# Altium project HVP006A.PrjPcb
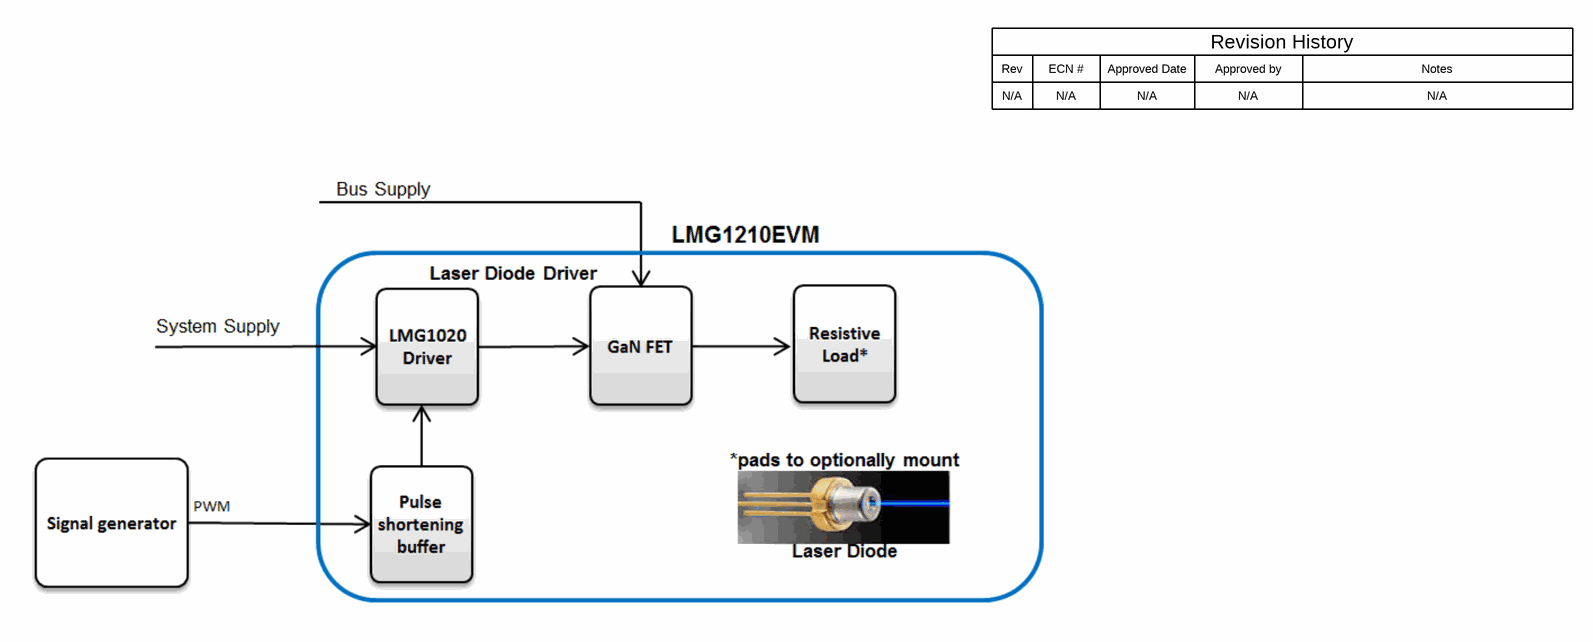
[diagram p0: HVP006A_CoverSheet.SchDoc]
CopyrightYear: 2017; EVM_orderable_num: LMG1020EVM-006; PCB_Layout: Alberto Doronzo; PCB_Rev: A; PRJ_Customer: Public Release; PRJ_Engineer: Alberto Doronzo; PRJ_Number: HPV006; PRJ_Title: LMG1020EVM; SCH_Rev: A; TechSupport: http://www.ti.com/support; TID: N/A
3 sheets, 56 parts. Net scope: global (net labels, ports and power ports of the same name join across sheets).
Board file: HVP006A.PcbDoc
Sheets:
  HVP006A_CoverSheet.SchDoc
  HVP006A.SchDoc
  HVP006A_EVM_Hardware.SchDoc

## Sheet HVP006A_CoverSheet.SchDoc
size 431 x 279 mm; Date: Not shown in title block; ApprovedBy: Not shown in title block; CheckedBy: Not shown in title block; Author: Not shown in title block; CompanyName: Not shown in title block; Engineer: Not shown in title block; Organization: Not shown in title block; Address1: Not shown in title block; Address2: Not shown in title block; Address3: Not shown in title block; Address4: Not shown in title block; DocumentNumber: 1; Revision: Use project parameter SCH_Rev; SheetNumber: 1; SheetTotal: 3; PageSetup: Record=PageOptions¦CenterHorizontal=True¦CenterVertical=True¦PrintScale=1.00¦XCorrection=1.00¦YCorrection=1.00¦PrintKind=0¦BorderSize=5000000¦LeftOffset=0¦BottomOffset=0¦Orientation=2¦PaperLength=1000¦PaperWidth=1000¦Scale=100¦PaperSource=15¦PrintQuality=600¦MediaType=1¦DitherType=10¦PaperKind=Letter¦PrintScaleMode=1

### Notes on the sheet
- Rev
- N/A
- ECN #
- Approved Date
- Approved by
- Revision History
- Notes

## Sheet HVP006A.SchDoc
size 431 x 279 mm; Date: Not shown in title block; ApprovedBy: Not shown in title block; CheckedBy: Not shown in title block; Author: Not shown in title block; CompanyName: Not shown in title block; Engineer: Not shown in title block; Organization: Not shown in title block; Address1: Not shown in title block; Address2: Not shown in title block; Address3: Not shown in title block; Address4: Not shown in title block; DocumentNumber: 1; Revision: Use project parameter SCH_Rev; SheetNumber: 2; SheetTotal: 3; PageSetup: Record=PageOptions¦CenterHorizontal=True¦CenterVertical=True¦PrintScale=0.64¦XCorrection=1.00¦YCorrection=1.00¦PrintKind=0¦BorderSize=5000000¦LeftOffset=0¦BottomOffset=0¦Orientation=2¦PaperLength=1000¦PaperWidth=1000¦Scale=100¦PaperSource=15¦PrintQuality=600¦MediaType=1¦DitherType=10¦PrintScaleMode=1¦PaperKind=Letter
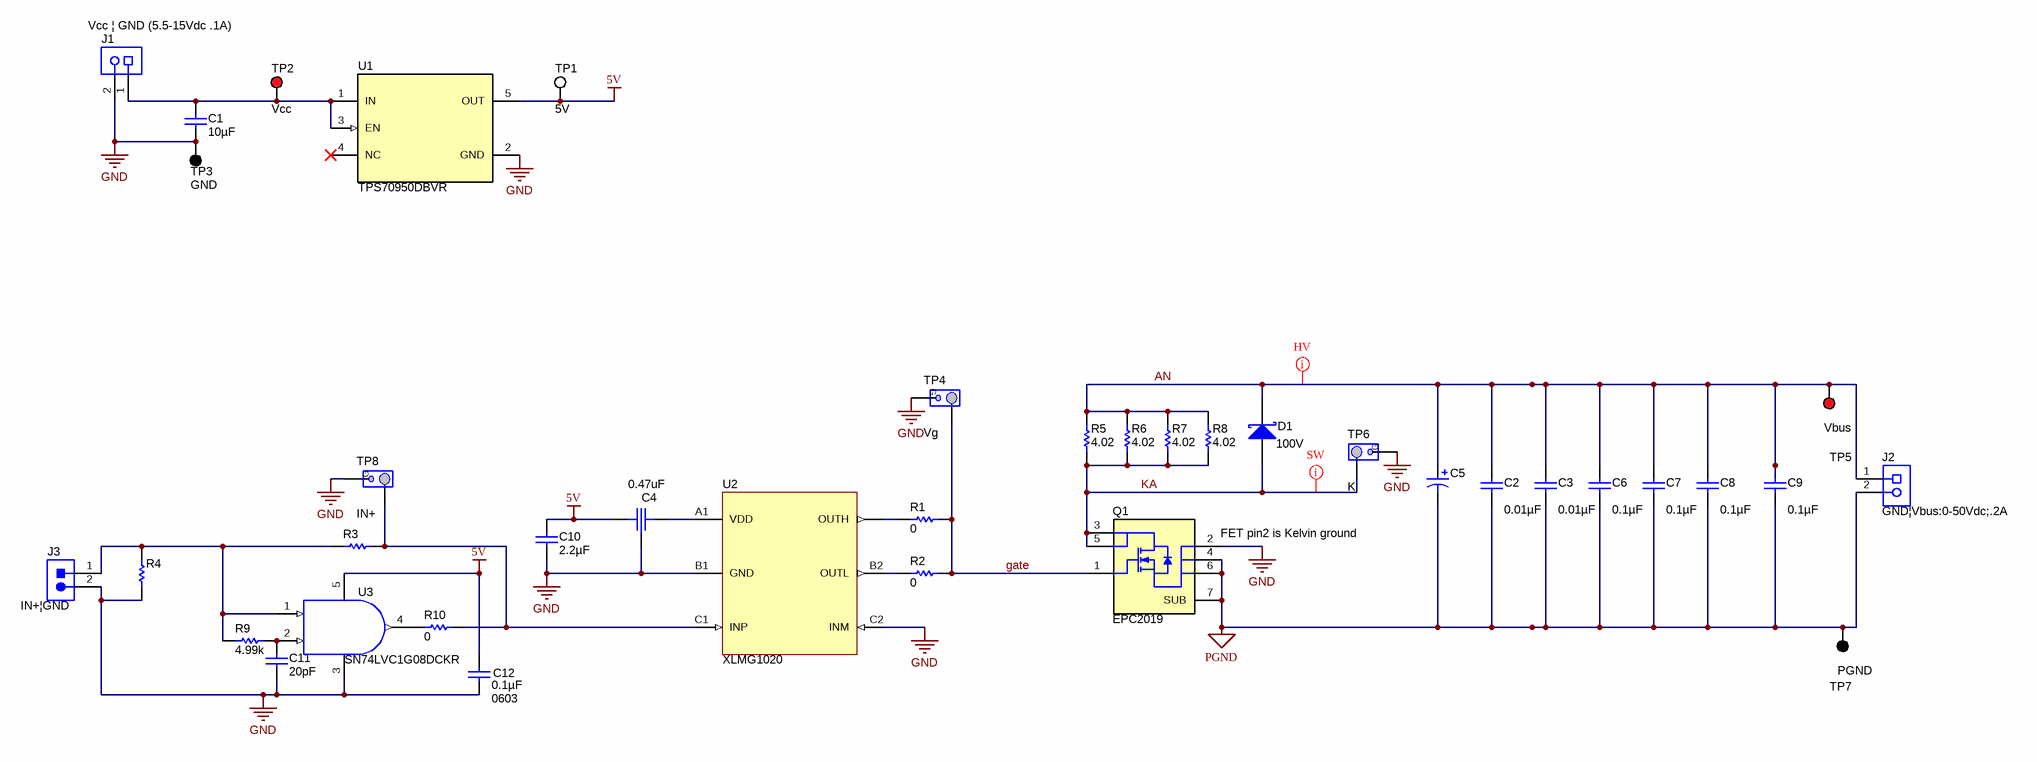
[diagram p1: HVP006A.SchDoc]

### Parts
C1  ValueDisplayed: 10µF  [1206]
C2  ValueDisplayed: 0.01µF  [0805L]  (hidden comment: C0805C103F1GACTU)
C3  ValueDisplayed: 0.01µF  [0805L]  (hidden comment: C0805C103F1GACTU)
C4  value 0.47uF  [YFF18PW]  (hidden comment: YFF18PW0J474M)
C5  DNP  [UUX_800x620]  (value not drawn)
C6  ValueDisplayed: 0.1µF  [0603L]  (hidden comment: GRM188R72A104KA35D)
C7  ValueDisplayed: 0.1µF  [0603L]  (hidden comment: GRM188R72A104KA35D)
C8  ValueDisplayed: 0.1µF  [0603L]  (hidden comment: GRM188R72A104KA35D)
C9  ValueDisplayed: 0.1µF  [0603L]  (hidden comment: GRM188R72A104KA35D)
C10  ValueDisplayed: 2.2µF  [0306]  (hidden comment: LWK107BJ225MV)
C11  ValueDisplayed: 20pF  [0402L]  (hidden comment: GRM1555C1H200JA01D)
C12  ValueDisplayed: 0.1µF  [0603]
D1  value 100V  [PowerDI123]  (hidden comment: DFLS2100-7)
J1  Vcc ¦ GND (5.5-15Vdc .1A)  [On-Shore_OSTVN02A150]
J2  GND¦Vbus:0-50Vdc;.2A  [TEC_282841-2]
J3  IN+¦GND  [Samtec_HTSW-102-07-G-S]
Q1  EPC2019  [EPC2019]
R1  ValueDisplayed: 0  [0201L]  (hidden comment: ERJ-1GE0R00C)
R2  ValueDisplayed: 0  [0201L]  (hidden comment: ERJ-1GE0R00C)
R3  CRCW040210R0JNED  [0402]  (value not drawn)
R4  DNP  [0603]  (value not drawn)
R5  ValueDisplayed: 4.02  [0603L]  (hidden comment: CRCW06034R02FKEA)
R6  ValueDisplayed: 4.02  [0603L]  (hidden comment: CRCW06034R02FKEA)
R7  ValueDisplayed: 4.02  [0603L]  (hidden comment: CRCW06034R02FKEA)
R8  ValueDisplayed: 4.02  [0603L]  (hidden comment: CRCW06034R02FKEA)
R9  ValueDisplayed: 4.99k  [0603]  (hidden comment: CR0603-FX-4991ELF)
R10  ValueDisplayed: 0  [0402]  (hidden comment: CRCW04020000Z0ED)
TP1  5V  [Testpoint_Keystone_Miniature]
TP2  Vcc  [Keystone5005]
TP3  GND  [Keystone5006]
TP4  Vg  [TP_PIGTAIL]  (no BOM)
TP5  Vbus  [Keystone5005]
TP6  K  [TP_PIGTAIL]  (no BOM)
TP7  PGND  [Keystone5006]
TP8  IN+  [TP_PIGTAIL]  (no BOM)
U1  TPS70950DBVR  [DBV0005A_N]
U2  XLMG1020  [YFF0006AAAA]
U3  SN74LVC1G08DCKR  [DCK0005A_N]

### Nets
5V: C4.1 C10.1 C12.1 TP1.1 U1.5(OUT) U3.5(V+)
GND: C1.1 C4.3 C10.2 C11.2 C12.2 J1.2 J3.2 Q1.2(S) R4.1 TP3.1 TP4.2 TP6.2 TP8.2 U1.2(GND) U2.B1(GND) U2.C2(INM) U3.3(V-)
PGND: C2.2 C3.2 C5.2(-) C6.2 C7.2 C8.2 C9.2 J2.2 Q1.4(S) Q1.6(S) Q1.7(SUB) TP7.1
AN: C2.1 C3.1 C5.1(+) C6.1 C7.1 C8.1 C9.1 D1.1(K) J2.1 R5.2 R6.2 R7.2 R8.2 TP5.1
gate: Q1.1(G) R1.2 R2.2 TP4.1
KA: D1.2(A) Q1.3(D) Q1.5(D) R5.1 R6.1 R7.1 R8.1 TP6.1
NetC1_2: C1.2 J1.1 TP2.1 U1.1(IN) U1.3(EN)
NetC4_2: C4.2 U2.A1(VDD)
NetC11_1: C11.1 R9.2 U3.2(B)
NetJ3_1: J3.1 R3.2 R4.2 R9.1 U3.1(A)
NetR1_1: R1.1 U2.A2(OUTH)
NetR2_1: R2.1 U2.B2(OUTL)
NetR3_1: R3.1 R10.2 TP8.1 U2.C1(INP)
NetR10_1: R10.1 U3.4(Y)

Not connected (* = marked no-connect by the designer): U1 4(NC)*

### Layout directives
net class HV: AN
net class SW: KA

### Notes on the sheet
- (near Q1) FET pin2 is Kelvin ground

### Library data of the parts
C1 = 885012208069: CAP, CERM, 10 µF, 25 V, +/- 10%, X7R, 1206; Manufacturer: Wurth Elektronik; Polarized: N; CompType: Capacitor; Value: 10uF; U/M: EA; Cap_F: 0.00001; Tolerance_%: 10; Value1: Unknown; VDC_V: 25; Value2: 25V; TaMin_C: -55; TaMax_C: 125; AEC Category: Q200
C2 C3 = C0805C103F1GACTU: CAP, CERM, 0.01 µF, 100 V, +/- 1%, C0G/NP0, 0805; Manufacturer: Kemet; Polarized: N; CompType: Capacitor; Value: 0.01uF; U/M: EA; Cap_F: 0.00000001; Tolerance_%: 1; Value1: Unknown; VDC_V: 100; Value2: 100V; TaMin_C: -55; TaMax_C: 125; Cap_Case: 0805; SizeArea_mm2: 2.5; SizeAreaWB_mm2: 6.75; SizeX_mm: 2; SizeY_mm: 1.25; SizeZ_mm: 1.45; AEC Category: Q200
C4 = YFF18PW0J474M: Feedthru Capacitor, 0.47uF, 6.3V, SMD; Manufacturer: TDK; SymbolCreator: a0411947; CompType: Filter
C5 = UUX2A4R7MCL1GS: CAP, AL, 4.7 µF, 100 V, +/- 20%, SMD; Manufacturer: Nichicon; Polarized: Y; CompType: Capacitor; Value: 4.7uF; ValueDisplayed: 4.7µF; U/M: EA; Cap_F: 0.0000047; Tolerance_%: 20; Value1: Unknown; VDC_V: 100; Value2: 100V; IRMS_A: 0.042; TaMin_C: -55; TaMax_C: 105; Cap_Case: 8x6.2mm; SizeAreaWB_mm2: 106.09; SizeArea_mm2: 68.89; SizeX_mm: 8.3; SizeZ_mm: 6.5; AEC Category: Q200; AEC Qualified: N
C6-C9 = GRM188R72A104KA35D: CAP, CERM, 0.1 µF, 100 V, +/- 10%, X7R, 0603; Manufacturer: MuRata; Polarized: N; CompType: Capacitor; Value: 0.1uF; U/M: EA; Cap_F: 0.0000001; Tolerance_%: 10; Value1: Unknown; VDC_V: 100; Value2: 100V; TaMin_C: -55; TaMax_C: 125; Cap_Case: 0603; SizeArea_mm2: 1.28; SizeAreaWB_mm2: 4.68; SizeX_mm: 1.6; SizeY_mm: 0.8; SizeZ_mm: 1; AEC Category: Q200
C10 = LWK107BJ105MV: CAP, CERM, 1 µF, 10 V, +/- 20%, X5R, 0306; Manufacturer: Taiyo Yuden; Polarized: N; CompType: Capacitor; Value: 2.2uF; U/M: EA; Cap_F: 0.0000022; Tolerance_%: 20; Value1: Unknown; VDC_V: 10; Value2: 10V; TaMin_C: -55; TaMax_C: 85; AEC Category: Q200
C11 = GRM1555C1H200JA01D: CAP, CERM, 20 pF, 50 V, +/- 5%, C0G/NP0, 0402; Manufacturer: MuRata; Polarized: N; CompType: Capacitor; Value: 20pF; U/M: EA; Cap_F: 0.00000000002; Tolerance_%: 5; Value1: Unknown; VDC_V: 50; Value2: 50V; TaMin_C: -55; TaMax_C: 125; Cap_Case: 0402; SizeArea_mm2: 0.5; SizeAreaWB_mm2: 3; SizeX_mm: 1; SizeZ_mm: 0.6; AEC Category: Q200
C12 = GRM188R71E104KA01D: CAP, CERM, 0.1uF, 25V, +/-10%, X7R, 0603; Manufacturer: MuRata; Polarized: N; CompType: Capacitor; U/M: EA; Cap_F: 0.0000001; Tolerance_%: 10; Value1: Unknown; VDC_V: 25; TaMin_C: -55; TaMax_C: 125
D1 = DFLS2100-7: Diode, Schottky, 100 V, 2 A, PowerDI123; Manufacturer: Diodes Inc.; U/M: EA; Vf_V: 0.86; Value1: 2A; Value2: 0.86V; Io_A: 2; Vr_V: 100; TJmax_C: 175; SizeAreaWB_mm2: 13.066; SizeArea_mm2: 6.586; SizeX_mm: 3.7; SizeY_mm: 1.78; SizeZ_mm: 0.98; AEC Category: Q101
J1 = OSTVN02A150: Terminal Block, 2.54mm, 2x1, Brass, TH; Manufacturer: On-Shore Technology; SymbolCreator: a0412235
J2 = 282841-2: Terminal Block, 2x1, 5.08mm, TH; Manufacturer: TE Connectivity; SymbolCreator: a0412235; U/M: EA
J3 = HTSW-102-07-G-S: Header, 100mil, 2x1, Gold, TH; Manufacturer: Samtec; SymbolCreator: a0412235
Q1 = EPC2019: MOSFET, N-CH, 200 V, 8.5 A, 2.766x0.68mm; Manufacturer: EPC; Alternate Manufacturer: None; SymbolCreator: Altium; U/M: EA; ChType: N; Value: 200V; VdsMax_V: 200; Value1: ? ohm; Value2: 1.8 nC; QgTyp_nC: 1.8; Vgs_V: 6; IdsMax_A: 8.5; SizeAreaWB_mm2: 7.3437; SizeArea_mm2: 2.6277; SizeX_mm: 2.766; SizeY_mm: 0.95; SizeZ_mm: 0.815; AEC Category: Q101
R1 R2 = CMP-0027011-3: RES, 0, 5%, 0.05 W, 0201; Manufacturer: Panasonic; Power_W: 50mW; TempCo: 600 ppm/C; Value_Code: 0000; U/M: EA; Value: 0; EIA_Code: E24; SizeX_mm: 0.6; SizeY_mm: 0.3; SizeZ_mm: 0.26; Value2: 0.05W; SizeArea_mm2: 0.18; CompType: Resistor; VDC_V: 15V; AEC Category: Q200
R3 = CRCW040210R0JNED: RES, 10, 5%, 0.063 W, 0402; Manufacturer: Vishay-Dale; CompType: Resistor; Value: 10; ValueDisplayed: DNP; Value_Code: 10R0; Tolerance_%: 5; Power_W: 0.063; Value2: 0.063W; VDC_V: 50; TempCo: 200 ppm/C; SizeArea_mm2: 0.5; SizeX_mm: 1; SizeZ_mm: 0.6; EIA_Code: E24; U/M: EA; AEC Category: Q200
R4 = CRCW060350R0FKEA: RES, 50, 1%, 0.1 W, 0603; Manufacturer: Vishay-Dale; CompType: Resistor; Value: 50; Value_Code: 50R0; Tolerance_%: 1; Power_W: 0.1; Value2: 0.1W; VDC_V: 75; TempCo: 100 ppm/C; SizeArea_mm2: 1.28; SizeX_mm: 1.6; SizeY_mm: 0.8; U/M: EA; AEC Category: Q200
R5-R8 = CMP-0022469-2: RES, 4.02, 1%, 0.1 W, 0603; Manufacturer: Vishay-Dale; Power_W: 100mW; TempCo: 100 ppm/C; Value_Code: 4R02; U/M: EA; Value: 4.02; EIA_Code: E96; SizeX_mm: 1.6; SizeY_mm: 0.8; SizeZ_mm: 1; Value2: 0.1W; SizeArea_mm2: 1.28; CompType: Resistor; VDC_V: 75V; AEC Category: Q200
R9 = CR0603-FX-4991ELF: RES, 4.99 k, 1%, 0.1 W, 0603; Manufacturer: Bourns; CompType: Resistor; Value: 4.99k; Res_ohm: 4990; Value_Code: 4k99; Tolerance_%: 1; Power_W: 0.1; Value2: 0.1W; TempCo: 100 ppm/C; SizeArea_mm2: 1.28; SizeX_mm: 1.6; SizeY_mm: 0.8; EIA_Code: E96; U/M: EA; AEC Category: Q200
R10 = CRCW04020000Z0ED: RES, 0, 5%, 0.063 W, 0402; Manufacturer: Vishay-Dale; CompType: Resistor; Value: 0; Value_Code: 0000; Tolerance_%: 5; Power_W: 0.063; Value2: 0.063W; VDC_V: 50; TempCo: 200 ppm/C; SizeArea_mm2: 0.5; SizeX_mm: 1; SizeZ_mm: 0.6; EIA_Code: E24; U/M: EA; AEC Category: Q200
TP1 = 5015: Test Point, Miniature, SMT; Manufacturer: Keystone; CompType: Test Point Loop
TP2 TP5 = 5005: Test Point, Compact, Red, TH; Manufacturer: Keystone; CompType: Test Point Loop; U/M: EA
TP3 TP7 = 5006: Test Point, Compact, Black, TH; Manufacturer: Keystone; CompType: Test Point Loop; U/M: EA
TP4 TP6 TP8 = TP_PIGTAIL: Testpoint PCB footprint for pigtail probe; Manufacturer: Used in BOM report; SymbolVersion: use current date i.e. 2008-05-20; SymbolCreator: Use a-id; CompType: Used in some BOM reports.  Useful for finding later.; U/M: EA, IN, or GM
U1 = TPS70950DBVR: 150-mA, 30-V, 1-uA IQ Voltage Regulators with Enable, DBV0005A (SOT-5); Alternate PartNumber: TPS70950DBVT; Manufacturer: Texas Instruments; SymbolCreator: Altium; SizeArea_mm2: 8.12; SizeAreaWB_mm2: 14.82; SizeX_mm: 2.8; SizeY_mm: 2.9; SizeZ_mm: 1.45; CompType: IC; U/M: EA
U2 = XLMG1020: High Speed Gate Driver in WCSP Package, YFF; Manufacturer: Texas Instruments; SymbolCreator: Altium; CompType: IC; U/M: EA
U3 = SN74LVC1G08DCKR: Single 2-Input Positive-AND Gate, DCK0005A (SOT-5); Alternate PartNumber: SN74LVC1G08DCKT; Manufacturer: Texas Instruments; CompType: IC; SizeArea_mm2: 4.2; SizeAreaWB_mm2: 9.3; SizeX_mm: 2.1; SizeY_mm: 2; SizeZ_mm: 1.1; U/M: EA

## Sheet HVP006A_EVM_Hardware.SchDoc
size 431 x 279 mm; Date: Not shown in title block; ApprovedBy: Not shown in title block; CheckedBy: Not shown in title block; Author: Not shown in title block; CompanyName: Not shown in title block; Engineer: Not shown in title block; Organization: Not shown in title block; Address1: Not shown in title block; Address2: Not shown in title block; Address3: Not shown in title block; Address4: Not shown in title block; DocumentNumber: 1; Revision: Use project parameter SCH_Rev; SheetNumber: 3; SheetTotal: 3; PageSetup: Record=PageOptions¦CenterHorizontal=True¦CenterVertical=True¦PrintScale=1.00¦XCorrection=1.00¦YCorrection=1.00¦PrintKind=0¦BorderSize=5000000¦LeftOffset=0¦BottomOffset=0¦Orientation=2¦PaperLength=1000¦PaperWidth=1000¦Scale=100¦PaperSource=15¦PrintQuality=600¦MediaType=1¦DitherType=10¦PaperKind=Letter¦PrintScaleMode=1
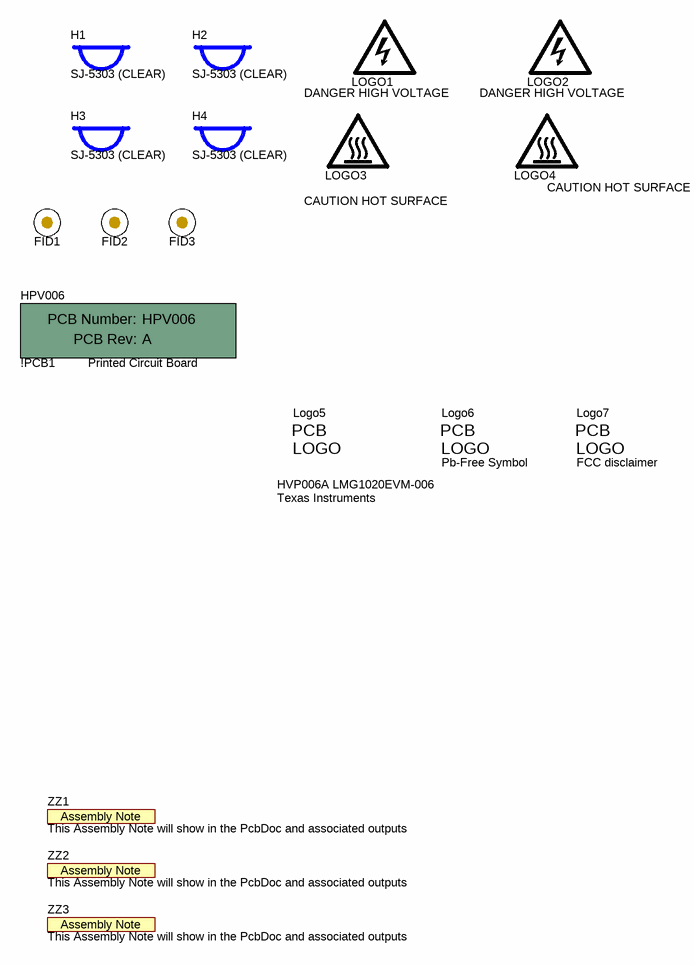
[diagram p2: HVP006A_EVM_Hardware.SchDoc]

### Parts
!PCB1  Printed Circuit Board  PartNumber: HPV006  (mechanical)
FID1  Fiducial  [Fiducial10-30]  (value not drawn)
FID2  Fiducial  [Fiducial10-30]  (value not drawn)
FID3  Fiducial  [Fiducial10-30]  (value not drawn)
H1  SJ-5303 (CLEAR)  [Bumpon_SJ5003Transparent]
H2  SJ-5303 (CLEAR)  [Bumpon_SJ5003Transparent]
H3  SJ-5303 (CLEAR)  [Bumpon_SJ5003Transparent]
H4  SJ-5303 (CLEAR)  [Bumpon_SJ5003Transparent]
LOGO1  DANGER HIGH VOLTAGE  [IEC_HighVoltage_Small]  (no BOM)
LOGO2  DANGER HIGH VOLTAGE  [IEC_HighVoltage_Small]  (no BOM)
LOGO3  CAUTION HOT SURFACE  [IEC_HotSurface_Small]  (no BOM)
LOGO4  CAUTION HOT SURFACE  [IEC_HotSurface_Small]  (no BOM)
Logo5  HVP006A LMG1020EVM-006  comment1: Texas Instruments  [TI_Stacked_Overlay_Small]  (no BOM)
Logo6  Pb-Free Symbol  [Pb-Free_Overlay_Small]  (no BOM)
Logo7  FCC disclaimer  [FCC_disclaimer]  (no BOM)
ZZ1  This Assembly Note will show in the PcbDoc and associated outputs  [AssemblyNote]  (no BOM)
ZZ2  This Assembly Note will show in the PcbDoc and associated outputs  [AssemblyNote]  (no BOM)
ZZ3  This Assembly Note will show in the PcbDoc and associated outputs  [AssemblyNote]  (no BOM)

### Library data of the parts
!PCB1 = PCB: Manufacturer: Any; SymbolCreator: a0412235
FID1-FID3 = Fiducial: Fiducial mark.  There is nothing to buy or mount.; SymbolCreator: codlsc
H1-H4 = SJ-5303 (CLEAR): Bumpon, Hemisphere, 0.44 X 0.20, Clear; Manufacturer: 3M; SymbolCreator: a0412235; Green_Lifecycle: Active; Green_REACh: Passed
LOGO1 LOGO2 = IEC_HighVoltage: IEC 61010-1 High Voltage Warning; SymbolCreator: a0412235
LOGO3 LOGO4 = IEC_HotSurface: IEC 61010-1 Hot Surface Warning; SymbolCreator: a0412235
Logo5 = TI_Logo: Texas Instrument Corporate Signature; SymbolCreator: a0412235
Logo6 = Pb-Free: SymbolCreator: a0412235
Logo7 = FCC_disclaimer: SymbolCreator: a0412235
ZZ1-ZZ3 = AssemblyNote: SymbolCreator: codlsc

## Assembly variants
001: not fitted C5 FID1 FID2 FID3 R3 R4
